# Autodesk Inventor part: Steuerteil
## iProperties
Created: 2007-03
Part Number: Steuerteil
Cost Center: 0 kg
Material: S235JRG2
Document SubType Name: Blech
Designer: Chako
Authority: 0 mm^3
Laenge: 2800,00 mm
Breite: 800,00 mm
Winkel_Standfläche: -8,00 grd
SaveDate: 2007-03-16
SaveTime: 17:06
FileName: Steuerteil_GVB2
TotalMass: 0 kg
TotalVolume: 0 mm^3
SM_Thickness: 0,5 mm
SM_Style: Standard
SM_Extents: N/A
SM_Extents_Width: 0,00 mm
SM_Extents_Length: 0,00 mm
Author: Chako
